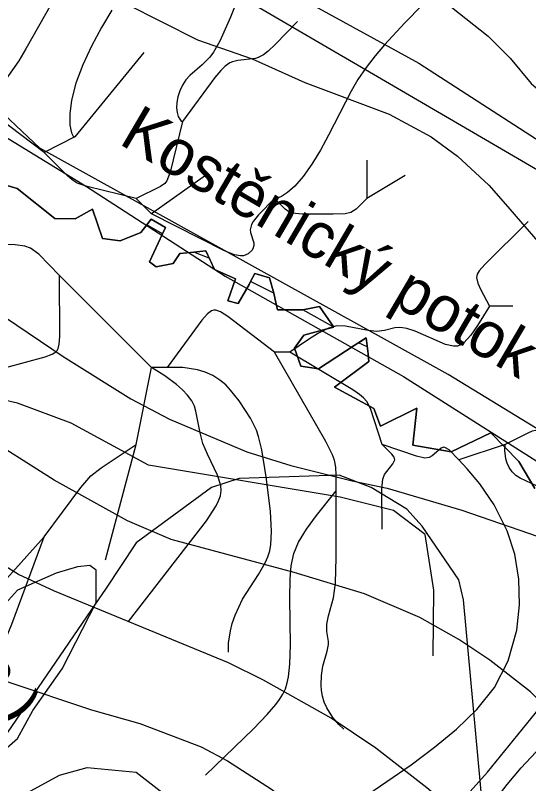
# Model space of a CAD drawing. Extents: x -709584 to -702006, y -1161789 to -1157496.
# Drawn here: x -707906.4 to -707739.3, y -1158652.2 to -1158402.5 of the extents above; entities that cross this region are included whole.
import ezdxf

# ---------------------------------------------------------------- set-up
doc = ezdxf.new("R2010")
doc.units = 0
for name, color, linetype in [('102_obvod PÚ', 7, 'Continuous'), ('103_hranice KÚ', 7, 'Continuous'), ('120_vrstevnice hlavní', 7, 'Continuous'), ('122_vrstevnice základní', 7, 'Continuous'), ('208_vodní plocha_KN', 7, 'Continuous'), ('408_BPEJ_linie', 7, 'Continuous'), ('411_akumulovaný odtok', 7, 'Continuous'), ('419_LPIS PB', 7, 'Continuous'), ('501_vodní tok', 7, 'Continuous'), ('502_vodní tok_popis', 7, 'Continuous')]:
    doc.layers.add(name, color=color, linetype=linetype)

msp = doc.modelspace()

# ---------------------------------------------------------------- linework, layer by layer
at = {"layer": '102_obvod PÚ'}
msp.add_lwpolyline([(-707916.19, -1158455.69), (-707905.81, -1158458.72), (-707893.49, -1158468.51), (-707886.9, -1158468.58), (-707881.2, -1158465.52), (-707877.96, -1158475.06), (-707872.24, -1158475.81), (-707865.54, -1158473.09), (-707863.53, -1158470.54), (-707862.1, -1158468.72), (-707857.5, -1158471.45), (-707858.45, -1158473.5), (-707862.64, -1158482.56), (-707860.56, -1158484.19), (-707855.04, -1158483.15), (-707852.83, -1158479.91), (-707848.26, -1158479.43), (-707844.37, -1158479.03), (-707841.54, -1158485.08), (-707834.75, -1158488.14), (-707837.24, -1158495.25), (-707833.84, -1158496.16), (-707830.3, -1158489.91), (-707829.77, -1158488.98), (-707828.44, -1158486.37), (-707823.68, -1158487.84), (-707822.26, -1158492.81), (-707821.79, -1158494.87), (-707821.02, -1158498.21), (-707816.1, -1158498.18), (-707812.79, -1158498.16), (-707807.42, -1158497.07), (-707802.74, -1158503.8), (-707805.27, -1158504.49), (-707812.46, -1158506.45), (-707815.5, -1158510.67), (-707813.44, -1158516.55), (-707807.67, -1158517.35), (-707796.08, -1158509.85), (-707792.16, -1158507.31), (-707791.57, -1158512.52), (-707791.29, -1158514.99), (-707802.51, -1158523.33), (-707789.64, -1158530.3), (-707787.5, -1158535.99), (-707775.66, -1158530.2), (-707776.98, -1158542.16), (-707764.48, -1158544.37), (-707751.63, -1158538.23), (-707742.45, -1158547.56), (-707737.26, -1158556.26)], dxfattribs=at)
at = {"layer": '103_hranice KÚ'}
msp.add_lwpolyline([(-707737.26, -1158556.26), (-707742.45, -1158547.56), (-707751.63, -1158538.23), (-707764.48, -1158544.37), (-707776.98, -1158542.16), (-707775.66, -1158530.2), (-707787.5, -1158535.99), (-707789.64, -1158530.3), (-707802.51, -1158523.33), (-707791.29, -1158514.99), (-707791.57, -1158512.52), (-707792.16, -1158507.31), (-707796.08, -1158509.85), (-707807.67, -1158517.35), (-707813.44, -1158516.55), (-707815.5, -1158510.67), (-707812.46, -1158506.45), (-707805.27, -1158504.49), (-707802.74, -1158503.8), (-707807.42, -1158497.07), (-707812.79, -1158498.16), (-707816.1, -1158498.18), (-707821.02, -1158498.21), (-707821.79, -1158494.87), (-707822.26, -1158492.81), (-707823.68, -1158487.84), (-707828.44, -1158486.37), (-707829.77, -1158488.98), (-707830.3, -1158489.91), (-707833.84, -1158496.16), (-707837.24, -1158495.25), (-707834.75, -1158488.14), (-707841.54, -1158485.08), (-707842.65, -1158482.71), (-707844.37, -1158479.03), (-707848.26, -1158479.43), (-707852.83, -1158479.91), (-707855.04, -1158483.15), (-707860.56, -1158484.19), (-707862.64, -1158482.56), (-707858.45, -1158473.5), (-707857.5, -1158471.45), (-707862.1, -1158468.72), (-707863.53, -1158470.54), (-707865.54, -1158473.09), (-707872.24, -1158475.81), (-707877.96, -1158475.06), (-707881.21, -1158465.51), (-707886.9, -1158468.58), (-707893.49, -1158468.51), (-707905.81, -1158458.72), (-707916.19, -1158455.69)], dxfattribs=at)
msp.add_lwpolyline([(-707737.26, -1158556.26), (-707742.45, -1158547.56), (-707751.63, -1158538.23), (-707764.48, -1158544.37), (-707776.98, -1158542.16), (-707775.66, -1158530.2), (-707787.5, -1158535.99), (-707789.64, -1158530.3), (-707802.51, -1158523.33), (-707791.29, -1158514.99), (-707791.57, -1158512.52), (-707792.16, -1158507.31), (-707796.08, -1158509.85), (-707807.67, -1158517.35), (-707813.44, -1158516.55), (-707815.5, -1158510.67), (-707812.46, -1158506.45), (-707805.27, -1158504.49), (-707802.74, -1158503.8), (-707807.42, -1158497.07), (-707812.79, -1158498.16), (-707816.1, -1158498.18), (-707821.02, -1158498.21), (-707821.79, -1158494.87), (-707822.26, -1158492.81), (-707823.68, -1158487.84), (-707828.44, -1158486.37), (-707829.77, -1158488.98), (-707830.3, -1158489.91), (-707833.84, -1158496.16), (-707837.24, -1158495.25), (-707834.75, -1158488.14), (-707841.54, -1158485.08), (-707842.65, -1158482.71), (-707844.37, -1158479.03), (-707848.26, -1158479.43), (-707852.83, -1158479.91), (-707855.04, -1158483.15), (-707860.56, -1158484.19), (-707862.64, -1158482.56), (-707858.45, -1158473.5), (-707857.5, -1158471.45), (-707862.1, -1158468.72), (-707863.53, -1158470.54), (-707865.54, -1158473.09), (-707872.24, -1158475.81), (-707877.96, -1158475.06), (-707881.21, -1158465.51), (-707886.9, -1158468.58), (-707893.49, -1158468.51), (-707905.81, -1158458.72), (-707916.19, -1158455.69)], dxfattribs=at)
at = {"layer": '120_vrstevnice hlavní'}
for points in [[(-707764.46, -1158399.84), (-707752.46, -1158409.27), (-707745.31, -1158416.42), (-707738.46, -1158424.56), (-707733.6, -1158428.84), (-707725.74, -1158433.99), (-707694.45, -1158446.56), (-707686.45, -1158447.7), (-707657.31, -1158448.42), (-707648.31, -1158449.7), (-707628.7, -1158454.43), (-707609.02, -1158462.28), (-707599.59, -1158466.28), (-707577.16, -1158480.7)], [(-707583.59, -1158875.87), (-707606.73, -1158863.86), (-707617.59, -1158856.86), (-707631.59, -1158846.01), (-707637.45, -1158840.86), (-707648.59, -1158827.86), (-707658.74, -1158812.43), (-707664.88, -1158802.15), (-707672.17, -1158786.72), (-707682.17, -1158761), (-707687.45, -1158750.72), (-707699.31, -1158730.15), (-707710.45, -1158714.14), (-707729.74, -1158692.57), (-707752.74, -1158670.43), (-707772.46, -1158653.57), (-707789.03, -1158640.71), (-707803.6, -1158631), (-707825.6, -1158618.57), (-707837.03, -1158613), (-707893.61, -1158589.71), (-707905.32, -1158584.28), (-707920.61, -1158574.85)]]:
    msp.add_lwpolyline(points, dxfattribs=at)
at = {"layer": '122_vrstevnice základní'}
for points in [[(-707907.18, -1158326.41), (-707901.6, -1158337.84), (-707895.75, -1158346.41), (-707887.46, -1158355.13), (-707880.32, -1158360.84), (-707873.32, -1158365.41), (-707863.32, -1158370.7), (-707843.32, -1158379.56), (-707811.03, -1158398.27), (-707775.03, -1158417.99), (-707695.74, -1158469.13), (-707686.74, -1158473.56), (-707678.17, -1158477.28), (-707650.74, -1158485.56), (-707633.59, -1158491.99)], [(-707909.75, -1158360.7), (-707903.03, -1158369.27), (-707884.03, -1158389.27), (-707876.46, -1158394.99), (-707870.32, -1158398.7), (-707847.03, -1158410.42), (-707829.32, -1158416.56), (-707812.17, -1158424.27), (-707784.74, -1158434.56), (-707771.03, -1158441.99), (-707762.46, -1158448.27), (-707752.31, -1158457.7), (-707746.88, -1158463.85)], [(-707746.88, -1158463.85), (-707726.6, -1158487.28), (-707714.03, -1158504.13), (-707711.31, -1158506.99), (-707703.74, -1158518.42), (-707696.31, -1158527.14), (-707683.02, -1158539.56), (-707646.8, -1158568.99), (-707641.17, -1158575.99)], [(-707909.61, -1158500.71), (-707890.75, -1158513.42), (-707868.75, -1158527.14)], [(-707868.75, -1158527.14), (-707856.18, -1158533.71), (-707831.03, -1158544.42), (-707816.75, -1158548.85), (-707796.74, -1158553.85), (-707785.32, -1158556.14), (-707761.05, -1158563.32), (-707699.13, -1158584.7), (-707675.14, -1158593.86), (-707655.96, -1158598.22), (-707648.54, -1158596.47), (-707643.75, -1158590.37), (-707640.69, -1158582.95), (-707641.17, -1158575.99)], [(-707583.31, -1158756.15), (-707591.88, -1158757.57), (-707597.59, -1158757.72), (-707603.31, -1158757), (-707614.73, -1158752.57), (-707620.73, -1158749), (-707629.02, -1158742.72), (-707635.59, -1158736.72), (-707655.59, -1158714.43), (-707679.02, -1158683), (-707692.31, -1158667.28), (-707701.6, -1158657.86), (-707718.17, -1158642.86), (-707738.74, -1158622.43), (-707751.88, -1158612.14), (-707762.03, -1158605.42), (-707774.74, -1158598.28), (-707792.74, -1158590.57), (-707815.6, -1158583.57), (-707855.6, -1158572.85), (-707869.89, -1158566.85), (-707893.75, -1158553.56), (-707918.46, -1158537.99)], [(-707908.75, -1158619.14), (-707881.6, -1158628.28), (-707865.89, -1158632.71), (-707845.89, -1158640.28), (-707837.32, -1158644.86), (-707823.03, -1158654), (-707808.46, -1158665.43), (-707780.46, -1158692.29), (-707754.88, -1158718.43), (-707739.74, -1158736.72), (-707725.17, -1158756.72), (-707714.17, -1158774.29), (-707708.74, -1158785.01), (-707690.74, -1158826.72), (-707685.31, -1158838.15), (-707679.45, -1158848.15), (-707672.88, -1158857.15), (-707668.02, -1158862.72), (-707643.45, -1158885.87), (-707620.45, -1158908.87), (-707584.45, -1158941.44)]]:
    msp.add_lwpolyline(points, dxfattribs=at)
at = {"layer": '208_vodní plocha_KN'}
for p, q in [((-707863.53, -1158470.54), (-707862.1, -1158468.72)), ((-707862.1, -1158468.72), (-707857.5, -1158471.45)), ((-707858.45, -1158473.5), (-707863.53, -1158470.54)), ((-707857.5, -1158471.45), (-707858.45, -1158473.5)), ((-707848.26, -1158479.43), (-707844.37, -1158479.03)), ((-707843.28, -1158481.37), (-707848.26, -1158479.43)), ((-707844.37, -1158479.03), (-707843.28, -1158481.37)), ((-707829.77, -1158488.98), (-707828.44, -1158486.37)), ((-707828.44, -1158486.37), (-707823.68, -1158487.84)), ((-707823.68, -1158487.84), (-707822.26, -1158492.81)), ((-707822.26, -1158492.81), (-707829.77, -1158488.98)), ((-707812.79, -1158498.16), (-707807.42, -1158497.07)), ((-707807.42, -1158497.07), (-707802.74, -1158503.8)), ((-707802.74, -1158503.8), (-707812.79, -1158498.16)), ((-707794.66, -1158508.93), (-707792.16, -1158507.31)), ((-707792.16, -1158507.31), (-707791.82, -1158510.28)), ((-707791.82, -1158510.28), (-707794.66, -1158508.93))]:
    msp.add_line(p, q, dxfattribs=at)
at = {"layer": '408_BPEJ_linie'}
for points in [[(-707564, -1158544.5), (-707609, -1158520), (-707620.24, -1158514.97), (-707661.5, -1158496.5), (-707846.5, -1158388.5), (-707862, -1158376), (-707894.5, -1158354.5), (-707897.13, -1158352.84), (-707897.93, -1158352.24)], [(-707600, -1158939), (-707609, -1158922), (-707648, -1158862.5), (-707678.5, -1158806.5), (-707697.5, -1158754.5), (-707703, -1158745), (-707739.5, -1158696), (-707753.5, -1158669), (-707760.5, -1158592.5), (-707762, -1158586), (-707774, -1158568.5), (-707779, -1158563), (-707790.5, -1158556), (-707801, -1158552), (-707833.5, -1158553), (-707842.5, -1158556), (-707867, -1158574), (-707877, -1158589), (-707880.39, -1158593.93), (-707914.77, -1158643.98)], [(-707908.5, -1158658.5), (-707892, -1158649.5), (-707883, -1158647), (-707867, -1158648.5), (-707851, -1158661), (-707838, -1158688), (-707836.5, -1158701.5), (-707837.5, -1158724), (-707845, -1158742), (-707856.5, -1158755.5), (-707874.5, -1158767), (-707889, -1158769), (-707917.5, -1158761)]]:
    msp.add_lwpolyline(points, dxfattribs=at)
at = {"layer": '411_akumulovaný odtok'}
for p, q in [((-707864.49, -1158414.5), (-707886.99, -1158442)), ((-707896.99, -1158447), (-707916.99, -1158432)), ((-707886.99, -1158442), (-707896.99, -1158447)), ((-707791.99, -1158449.5), (-707791.99, -1158462)), ((-707844.49, -1158454.5), (-707861.99, -1158467)), ((-707779.49, -1158454.5), (-707791.99, -1158462)), ((-707861.99, -1158467), (-707866.99, -1158462)), ((-707861.99, -1158517), (-707891.99, -1158487)), ((-707744.49, -1158497), (-707751.99, -1158497)), ((-707816.99, -1158512), (-707821.99, -1158512)), ((-707866.99, -1158542), (-707861.99, -1158517)), ((-707856.99, -1158517), (-707861.99, -1158517)), ((-707876.99, -1158579.5), (-707866.99, -1158542)), ((-707746.99, -1158542), (-707761.99, -1158547))]:
    msp.add_line(p, q, dxfattribs=at)
for points in [[(-707804.49, -1158349.5), (-707811.77, -1158356.57), (-707817.35, -1158362.37), (-707820.16, -1158365.79), (-707822.39, -1158369.27), (-707824.29, -1158373.07), (-707826.01, -1158377), (-707836.34, -1158403.07), (-707839.81, -1158410.83), (-707841.89, -1158414.4), (-707843.11, -1158416.02), (-707845.57, -1158418.49), (-707849.56, -1158421.99), (-707850.82, -1158423.46), (-707851.91, -1158425.15), (-707852.79, -1158426.99), (-707853.44, -1158428.9), (-707853.82, -1158430.77), (-707853.92, -1158432.53), (-707853.73, -1158434.08), (-707853.33, -1158435.31), (-707852.82, -1158436.23), (-707852.34, -1158436.82), (-707851.99, -1158437)], [(-707762.72, -1158387.59), (-707779.65, -1158404.91), (-707786.19, -1158411.99), (-707789.29, -1158415.62), (-707792.2, -1158419.37), (-707794.86, -1158423.26), (-707797.08, -1158427.13), (-707804.4, -1158441.39), (-707807.07, -1158446.29), (-707809.83, -1158450.84), (-707812.63, -1158454.8), (-707815.42, -1158457.99), (-707817.73, -1158460.01), (-707819.72, -1158461.34), (-707821.2, -1158462.01), (-707821.99, -1158462)], [(-707894.69, -1158398.77), (-707902.89, -1158413.37), (-707905.27, -1158417.2), (-707914.16, -1158429.7)], [(-707874.9, -1158400.8), (-707878.29, -1158406.44), (-707881.55, -1158412.42), (-707884.42, -1158418.51), (-707886.67, -1158424.47), (-707888.12, -1158430.05), (-707888.65, -1158434.48), (-707888.58, -1158438.11), (-707888.07, -1158440.66), (-707887.54, -1158441.69), (-707886.99, -1158442)], [(-707814.49, -1158404.5), (-707821.79, -1158411.98), (-707824.05, -1158414.06), (-707825.64, -1158415.26), (-707827.35, -1158416.17), (-707828.23, -1158416.45), (-707833.91, -1158417.18), (-707835.71, -1158417.57), (-707836.55, -1158417.9), (-707838.1, -1158418.96), (-707839.49, -1158420.35), (-707841.43, -1158422.71), (-707851.99, -1158437)], [(-707851.99, -1158437), (-707856.02, -1158453.41), (-707857.06, -1158456.22), (-707857.75, -1158457.11), (-707859.16, -1158458.15), (-707866.99, -1158462)], [(-707866.99, -1158462), (-707883.01, -1158458.05), (-707886.22, -1158457), (-707887.9, -1158455.98), (-707889.4, -1158454.67), (-707896.99, -1158447)], [(-707821.99, -1158462), (-707827.18, -1158467.28), (-707828.92, -1158469.5), (-707829.51, -1158470.49), (-707829.95, -1158472.23), (-707829.84, -1158473.09), (-707828.76, -1158476.46), (-707828.72, -1158477.26), (-707828.92, -1158478.03), (-707829.32, -1158478.75), (-707830.54, -1158479.97), (-707832.14, -1158480.65), (-707833.07, -1158480.69), (-707835.07, -1158480.28), (-707838.25, -1158479.01), (-707861.99, -1158467)], [(-707791.99, -1158462), (-707795.4, -1158465.42), (-707797.17, -1158466.56), (-707799.01, -1158466.95), (-707802.97, -1158467.06), (-707813, -1158467.05), (-707816.21, -1158466.74), (-707817.36, -1158466.3), (-707818.57, -1158465.42), (-707821.99, -1158462)], [(-707739.49, -1158469.5), (-707753.6, -1158483.49), (-707755.41, -1158485.52), (-707756.04, -1158486.58), (-707756.26, -1158487.7), (-707755.84, -1158489.49), (-707754.96, -1158491.43), (-707751.99, -1158497)], [(-707891.99, -1158487), (-707898.73, -1158480.13), (-707901.39, -1158478.2), (-707903.29, -1158477.47), (-707906.46, -1158477.05), (-707916.41, -1158476.91), (-707919.62, -1158476.6), (-707921.63, -1158476.09), (-707922.48, -1158475.71), (-707926.49, -1158473.52), (-707928.26, -1158473.1), (-707930.27, -1158473.22), (-707932.46, -1158473.72), (-707941.99, -1158477)], [(-707909.49, -1158517), (-707896.6, -1158513.49), (-707894.42, -1158512.65), (-707893.23, -1158511.9), (-707892.77, -1158511.41), (-707892.43, -1158510.81), (-707892.05, -1158509.37), (-707891.86, -1158506.92), (-707891.99, -1158487)], [(-707751.99, -1158497), (-707755.9, -1158503.34), (-707758.15, -1158506.48), (-707760.4, -1158508.9), (-707761.45, -1158509.59), (-707762.51, -1158509.96), (-707763.73, -1158510.02), (-707766.36, -1158509.44), (-707776.18, -1158505.19), (-707778.96, -1158504.27), (-707780.32, -1158504.01), (-707781.65, -1158503.95), (-707782.8, -1158504.09), (-707786.21, -1158504.97), (-707788.75, -1158505.25), (-707791.57, -1158504.97), (-707798.88, -1158503.54), (-707801.76, -1158503.45), (-707804.48, -1158504.15), (-707807.66, -1158505.74), (-707810.99, -1158507.81), (-707816.99, -1158512)], [(-707821.99, -1158512), (-707837.22, -1158500.36), (-707839.58, -1158498.89), (-707841.08, -1158498.35), (-707841.8, -1158498.33), (-707842.48, -1158498.55), (-707843.78, -1158499.49), (-707845.62, -1158501.56), (-707856.99, -1158517)], [(-707801.99, -1158557), (-707801.93, -1158551.97), (-707802.07, -1158549.36), (-707802.45, -1158547.13), (-707803.11, -1158545.34), (-707805.36, -1158541.02), (-707821.99, -1158512)], [(-707786.99, -1158542), (-707790.82, -1158530.3), (-707791.96, -1158528.04), (-707793.01, -1158526.76), (-707794.3, -1158525.68), (-707796.47, -1158524.23), (-707816.99, -1158512)], [(-707869.49, -1158599.5), (-707844.15, -1158566.84), (-707840.99, -1158561.92), (-707840.2, -1158560.27), (-707839.64, -1158558.62), (-707839.39, -1158556.95), (-707839.52, -1158555.31), (-707840.55, -1158551.99), (-707843.85, -1158545.18), (-707845.32, -1158541.62), (-707846.22, -1158538.14), (-707847.57, -1158531.15), (-707848.08, -1158529.48), (-707848.95, -1158527.75), (-707850.3, -1158525.93), (-707852, -1158524.17), (-707853.89, -1158522.52), (-707857.73, -1158519.69), (-707861.99, -1158517)], [(-707836.99, -1158609.5), (-707836.98, -1158606.63), (-707836.37, -1158602.52), (-707835.78, -1158600.14), (-707834.85, -1158597.47), (-707832.38, -1158592.31), (-707827.26, -1158584.3), (-707825.09, -1158580.51), (-707824.22, -1158578.55), (-707823.57, -1158576.54), (-707823.18, -1158574.49), (-707822.95, -1158570.24), (-707823.35, -1158563.65), (-707824.68, -1158552.51), (-707826.12, -1158543.69), (-707827.19, -1158539.41), (-707827.91, -1158537.36), (-707829.86, -1158533.38), (-707833.54, -1158527.79), (-707836.3, -1158524.3), (-707837.86, -1158522.63), (-707839.8, -1158521.02), (-707842.05, -1158519.58), (-707844.53, -1158518.44), (-707847.02, -1158517.69), (-707851.84, -1158516.99), (-707856.99, -1158517)], [(-707726.99, -1158542), (-707734.59, -1158538.14), (-707735.79, -1158537.63), (-707736.99, -1158537.38), (-707738.19, -1158537.63), (-707739.39, -1158538.14), (-707746.99, -1158542)], [(-707896.99, -1158572), (-707885.02, -1158555.97), (-707881.8, -1158552.2), (-707878.45, -1158549.59), (-707866.99, -1158542)], [(-707786.99, -1158569.5), (-707787.04, -1158556.35), (-707786.81, -1158553.3), (-707786.24, -1158551.69), (-707783.45, -1158548.22), (-707782.88, -1158546.97), (-707783.08, -1158546.13), (-707783.81, -1158545.1), (-707786.99, -1158542)], [(-707761.99, -1158547), (-707765.16, -1158543.75), (-707766.55, -1158542.91), (-707766.97, -1158542.87), (-707767.79, -1158543.18), (-707770.75, -1158545.63), (-707771.65, -1158546.18), (-707773.14, -1158546.42), (-707775.85, -1158545.79), (-707786.99, -1158542)], [(-707716.99, -1158607), (-707714.3, -1158597.34), (-707713.13, -1158591.63), (-707713.01, -1158588.64), (-707713.19, -1158587.2), (-707714.15, -1158584.32), (-707716.42, -1158580.14), (-707720.89, -1158573.27), (-707727.38, -1158563.77), (-707730.37, -1158560), (-707732.65, -1158557.85), (-707733.88, -1158556.99), (-707736.54, -1158555.56), (-707742.11, -1158552.97), (-707743.47, -1158552.01), (-707744.69, -1158550.82), (-707745.67, -1158549.44), (-707746.29, -1158548.05), (-707746.7, -1158546.61), (-707747.05, -1158543.98), (-707746.99, -1158542)], [(-707801.3, -1158662.43), (-707777.54, -1158646.09), (-707769.93, -1158640.44), (-707762.73, -1158634.52), (-707756.14, -1158628.16), (-707750.44, -1158621.03), (-707745.99, -1158612.29), (-707743.16, -1158602.33), (-707742.24, -1158594.07), (-707742.49, -1158585.73), (-707743.85, -1158577.64), (-707746.26, -1158570.1), (-707750.53, -1158561.63), (-707755.21, -1158554.81), (-707759.26, -1158549.93), (-707761.99, -1158547)], [(-707844.49, -1158649.5), (-707828.85, -1158634.38), (-707824.35, -1158629.76), (-707821.6, -1158626.57), (-707820.38, -1158624.92), (-707819.31, -1158623.2), (-707818.45, -1158621.4), (-707817.84, -1158619.51), (-707817.43, -1158617.54), (-707817, -1158613.43), (-707816.84, -1158607.07), (-707817, -1158592.01), (-707816.89, -1158585.61), (-707816.56, -1158581.44), (-707815.74, -1158577.42), (-707814.18, -1158573.74), (-707811.58, -1158569.56), (-707808.36, -1158565.11), (-707801.99, -1158557)], [(-707799.49, -1158634.5), (-707801.03, -1158633.04), (-707803.03, -1158630.71), (-707804.99, -1158627.64), (-707805.81, -1158625.74), (-707806.38, -1158623.81), (-707806.72, -1158621.95), (-707806.84, -1158620.25), (-707806.73, -1158617.08), (-707806.32, -1158614.02), (-707804.84, -1158609.19), (-707804.41, -1158607.06), (-707804.44, -1158606.01), (-707804.97, -1158602.79), (-707804.98, -1158600.36), (-707804.41, -1158597.64), (-707802.82, -1158591.86), (-707802.18, -1158587.03), (-707801.92, -1158578.73), (-707801.99, -1158557)], [(-707951.99, -1158627), (-707947.67, -1158624.83), (-707944.63, -1158623.05), (-707941.52, -1158620.81), (-707938.9, -1158618.45), (-707933.59, -1158612.73), (-707896.99, -1158572)], [(-707936.99, -1158652), (-707932.1, -1158644.48), (-707928.89, -1158638.43), (-707928.19, -1158636.63), (-707926.21, -1158629.01), (-707924.85, -1158626.13), (-707921.79, -1158622.1), (-707915.91, -1158615.66), (-707913.7, -1158612.97), (-707912.71, -1158611.56), (-707910.98, -1158608.53), (-707909.51, -1158605.34), (-707907.52, -1158600.41), (-707896.99, -1158572)], [(-707966.99, -1158867), (-707915.12, -1158808.86), (-707900.8, -1158793.19), (-707891.08, -1158782.94), (-707881.07, -1158772.99), (-707862.77, -1158756.1), (-707852.95, -1158746.56), (-707838.55, -1158731.85), (-707810.1, -1158702.11), (-707795.66, -1158687.61), (-707785.77, -1158678.41), (-707780.67, -1158674.07), (-707768.74, -1158664.56), (-707763.63, -1158660.05), (-707758.33, -1158654.76), (-707752.73, -1158648.5), (-707734.33, -1158626.01), (-707724.28, -1158614.6), (-707720.51, -1158610.52), (-707716.99, -1158607)], [(-707824.49, -1158754.5), (-707796.05, -1158722.91), (-707789.1, -1158714.9), (-707784.62, -1158709.44), (-707780.33, -1158703.73), (-707776.24, -1158697.77), (-707756.68, -1158667.29), (-707752.68, -1158661.27), (-707748.51, -1158655.38), (-707746.32, -1158652.52), (-707741.77, -1158647.15), (-707732.13, -1158636.86), (-707726.87, -1158630.61), (-707724.28, -1158627.03), (-707721.91, -1158623.32), (-707719.92, -1158619.61), (-707718.42, -1158616.04), (-707717.59, -1158613.23), (-707716.87, -1158608.83), (-707716.85, -1158607.53), (-707716.99, -1158607)]]:
    msp.add_lwpolyline(points, dxfattribs=at)
at = {"layer": '419_LPIS PB'}
msp.add_lwpolyline([(-707910.07, -1158441.67), (-707883.16, -1158458.14), (-707838.11, -1158487.27), (-707780.05, -1158519.9), (-707736.6, -1158547.4), (-707688.1, -1158576.1), (-707628.58, -1158608.07), (-707590.54, -1158631.17), (-707549.65, -1158650.05)], dxfattribs=at)
msp.add_lwpolyline([(-707921.63, -1158613.42), (-707923.63, -1158621.45), (-707923.63, -1158634.51), (-707921.13, -1158641.54), (-707917.62, -1158644.55), (-707912.62, -1158643.55), (-707905.61, -1158637.52), (-707900.61, -1158628.48), (-707891.09, -1158614.93), (-707880.08, -1158593.34), (-707880.08, -1158582.79), (-707882.09, -1158581.28), (-707886.09, -1158581.79), (-707893.1, -1158583.8), (-707905.61, -1158589.32), (-707911.62, -1158595.85)], close=True, dxfattribs=at)
at = {"layer": '501_vodní tok'}
for points in [[(-707570.15, -1158633.83), (-707601.12, -1158617.43), (-707623.72, -1158603.76), (-707643.39, -1158593.84), (-707731.22, -1158540.19), (-707765.45, -1158519.26), (-707785.24, -1158508.3), (-707898.35, -1158445.64), (-707919.84, -1158425.46)], [(-707770.36, -1158610.66), (-707770.12, -1158589.37), (-707773.03, -1158571.25), (-707783.24, -1158563.39), (-707800.68, -1158559.16), (-707863.04, -1158548.7), (-707888.19, -1158535.02), (-707905.68, -1158528.53), (-707926.81, -1158523.75)], [(-707770.36, -1158610.66), (-707770.12, -1158589.37), (-707773.03, -1158571.25), (-707783.24, -1158563.39), (-707800.68, -1158559.16), (-707863.04, -1158548.7), (-707888.19, -1158535.02), (-707905.68, -1158528.53), (-707926.81, -1158523.75)]]:
    msp.add_lwpolyline(points, dxfattribs=at)

# ---------------------------------------------------------------- texts
at = {"layer": '502_vodní tok_popis'}
for s, rotation, p in [('IDVT 10259782 (PVL, s.p.)', 299.004, (-708027.24, -1158423.76)), ('Kostěnický potok (PVL, s.p)', 329.5705, (-707873.06, -1158444.01))]:
    msp.add_text(s, height=15, rotation=rotation, dxfattribs=at).set_placement(p)

doc.saveas('drawing.dxf')
